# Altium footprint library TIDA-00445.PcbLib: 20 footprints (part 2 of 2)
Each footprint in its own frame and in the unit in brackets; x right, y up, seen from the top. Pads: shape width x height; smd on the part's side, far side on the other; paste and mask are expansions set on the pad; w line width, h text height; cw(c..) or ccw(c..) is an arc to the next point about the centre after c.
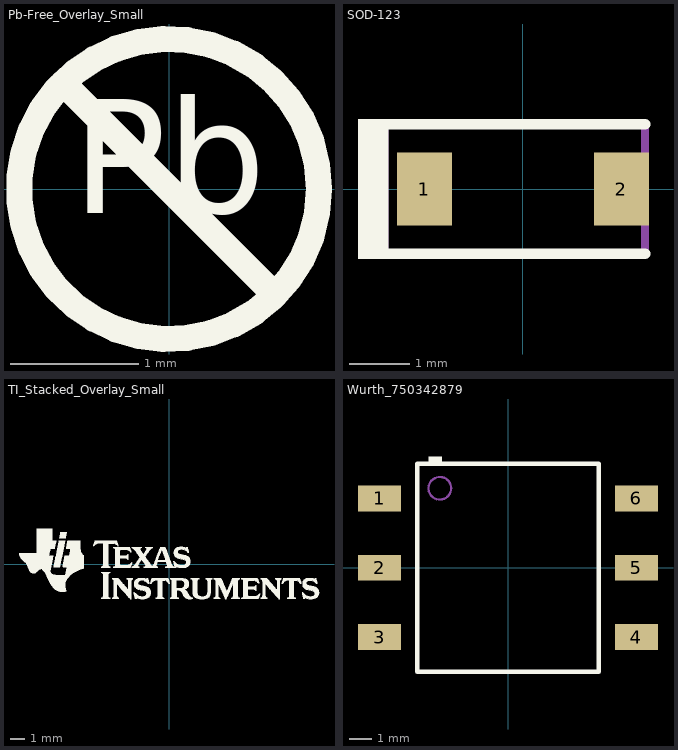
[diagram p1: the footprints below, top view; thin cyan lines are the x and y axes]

## Pb-Free_Overlay_Small [mm]
height 13
Top Overlay:
  circle w0.203: c0,0 r1.168
  lines w0.203: -0.826,0.826 0.826,-0.826
  text "Pb" at -0.752,-0.48 h1.52

## SOD-123 [mm] "On Semi recommended land pattern"
height 1.35
pads (2):
  rect 0.915x1.22 smd: 1(-1.637,0) 2(1.637,0)
Top Overlay:
  rectangle: -2.743,-1.168 -2.235,1.168
  lines w0.178: -2.413,-1.079 2.032,-1.079 ; -2.413,1.079 2.032,1.079
Mechanical 5:
  rectangle: -2.743,-1.168 -2.235,1.168
  lines w0.127: -2.413,-1.079 2.032,-1.079 2.032,1.079 -2.413,1.079
  text ".Designator" at -0.864,-0.508 h0.76
3D body: height 1.35, standoff 0, extent -1.932,-0.9 1.932,0.9

## TI_Stacked_Overlay_Small [mm]
height 13
Top Overlay:
  drawing of 18 lines, arcs and shapes, not listed

## Wurth_750342879 [mm] "SMD, 6-Leads, Body 9.14x8mm, Pitch 3.05mm"
height 7.62
pads (6):
  rect 1.9x1.14 smd: 1(-5.655,3.05) 2(-5.655,0) 3(-5.655,-3.05) 4(5.655,-3.05) 5(5.655,0) 6(5.655,3.05)
Top Overlay:
  rectangle: -3.5,4.57 -2.9,4.9
  lines w0.2: -4,-4.57 4,-4.57 4,4.57 -4,4.57 -4,-4.57
Mechanical 5:
  circle w0.1: c-3,3.5 r0.5
  lines w0.1: -4,-4.57 -4,4.57 4,4.57 4,-4.57 -4,-4.57
  text ".Designator" at -0.051,0.102 h0.76
3D body: height 6.5, standoff 5, extent -2,-4.57 2,4.57
3D body: height 7.82, standoff 6.5, extent -4,-4.57 4,4.57
3D body: height 5, standoff 0, extent -4,-4.57 4,4.57
3D body: height 7.83, standoff 7.8, extent -3.509,2.991 -2.491,4.009
3D body: height 0.8, standoff 0, extent -6.35,2.75 -3.849,3.35
3D body: height 0.8, standoff 0, extent -6.35,-0.3 -3.849,0.3
3D body: height 0.8, standoff 0, extent -6.35,-3.35 -3.849,-2.75
3D body: height 0.8, standoff 0, extent 3.849,-3.35 6.35,-2.75
3D body: height 0.8, standoff 0, extent 3.849,-0.3 6.35,0.3
3D body: height 0.8, standoff 0, extent 3.849,2.75 6.35,3.35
